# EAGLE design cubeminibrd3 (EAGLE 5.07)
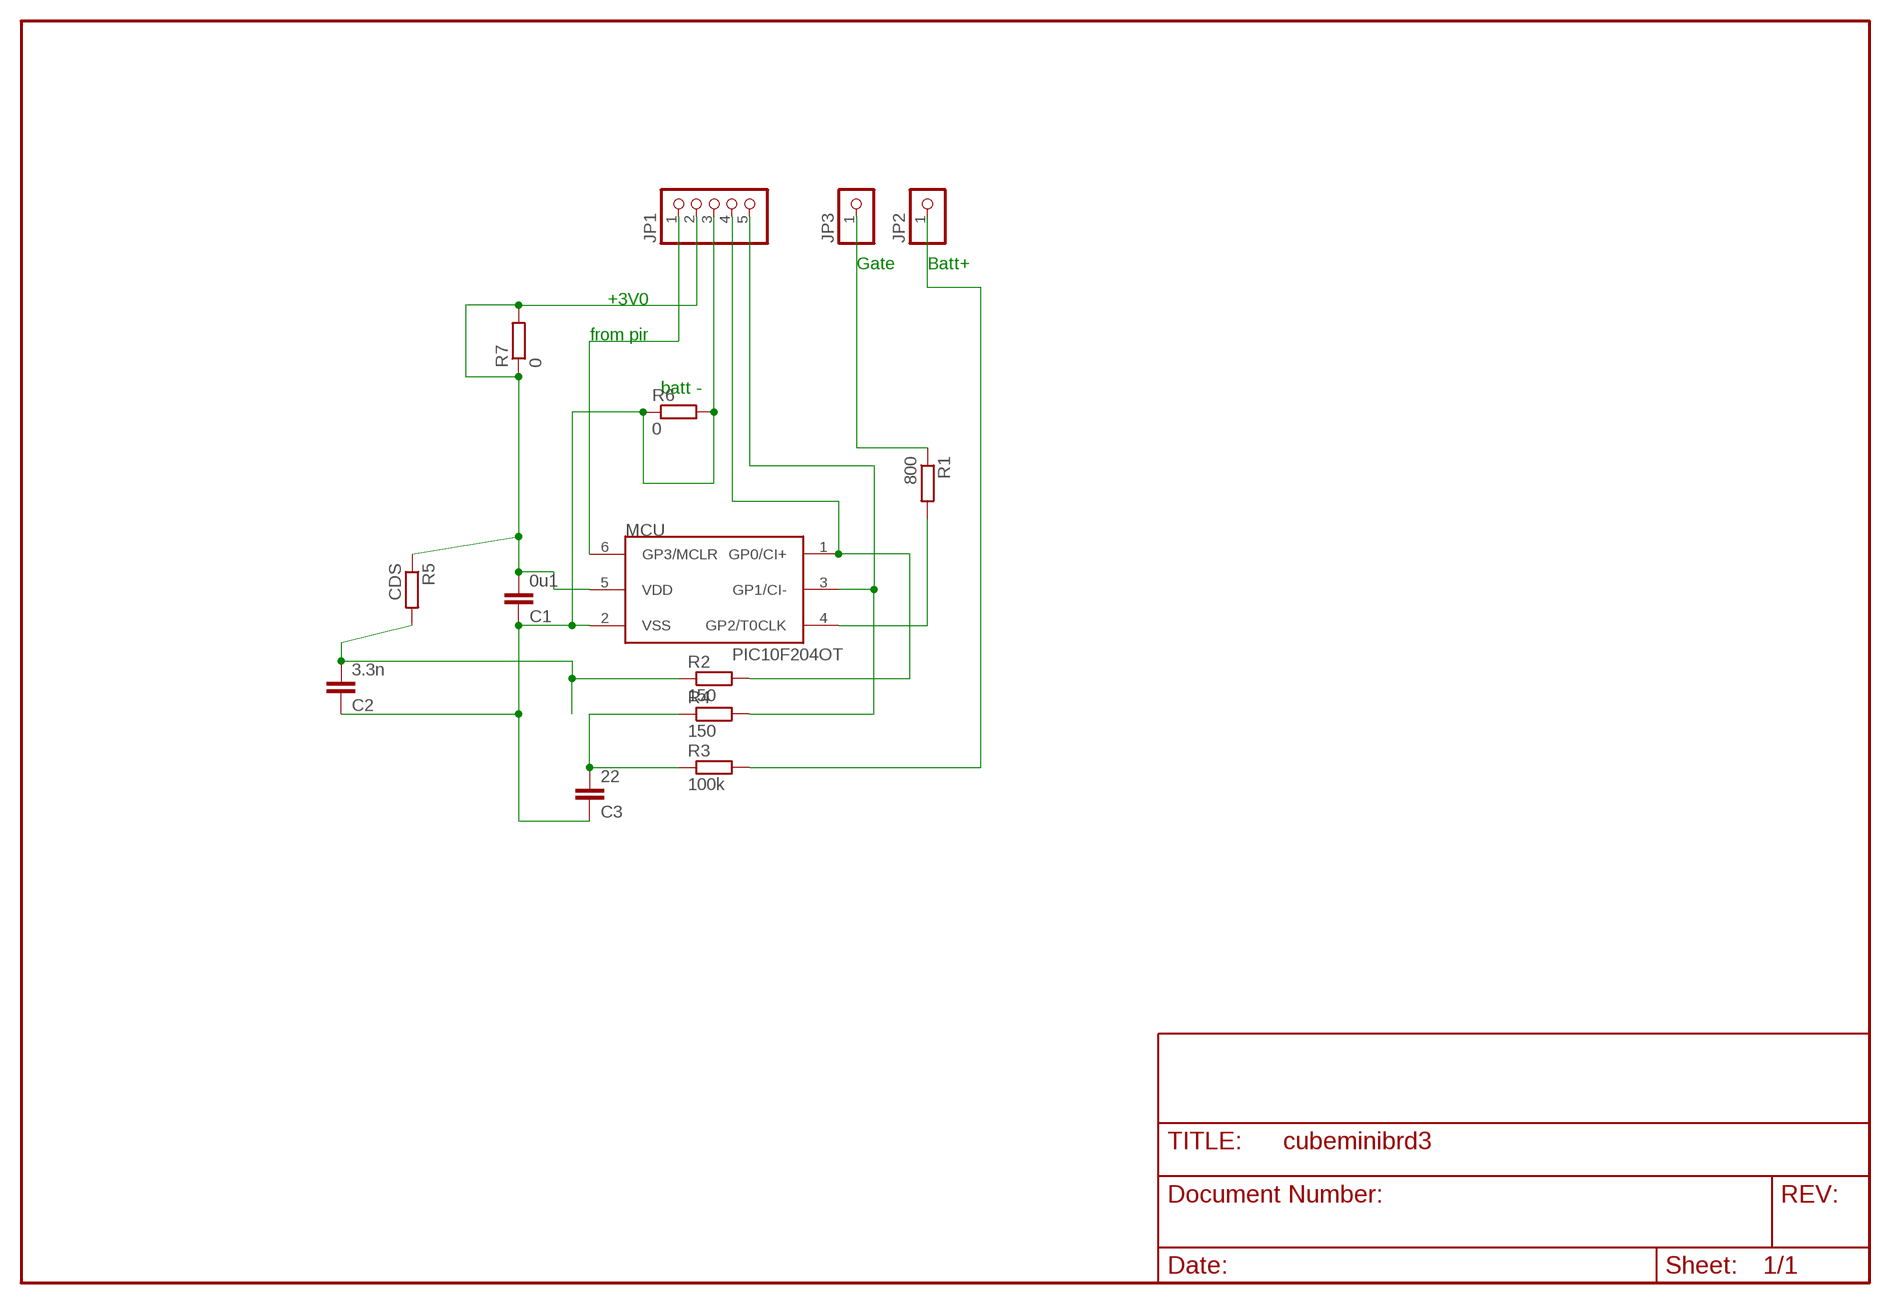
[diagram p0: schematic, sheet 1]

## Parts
C1  0u1  C-EUC1206  [C1206]
C2  3.3n  C-EUC1206  [C1206]
C3  22  C-EUC1206  [C1206]
JP1  PINHD-1X5  [1X05]
JP2  PINHD-1X1  [1X01]
JP3  PINHD-1X1  [1X01]
MCU  PIC10F204OT  [SOT23-6]
R1  800  R-EU_R1206  [R1206]
R2  150  R-EU_R1206  [R1206]
R3  100k  R-EU_R1206  [R1206]
R4  150  R-EU_R1206  [R1206]
R5  CDS  R-EU_0613/5V  [P0613V]
R6  0  R-EU_R1206  [R1206]
R7  0  R-EU_R1206  [R1206]

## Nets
N$1: JP3.1 R1.1
N$3: C2.2 R2.1 R5.2
N$4: JP1.4 MCU.1(GP0/CI+) R2.2
N$5: MCU.4(GP2/T0CLK) R1.2
N$7: C3.2 R3.1 R4.1
N$8: JP1.5 MCU.3(GP1/CI-) R4.2
PIR: JP1.1 MCU.6(GP3/MCLR)
V3: C1.2 JP1.2 MCU.5(VDD) R5.1 R7.1 R7.2
V+: JP2.1 R3.2
V-: C1.1 C2.1 C3.1 JP1.3 MCU.2(VSS) R6.1 R6.2

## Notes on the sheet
- Gate | Batt+
- +3V0
- from pir
- batt -

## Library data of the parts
C1-C3 = rcl:C-EU: CAPACITOR, European symbol
JP1 = pinhead:PINHD-1X5: PIN HEADER
JP2 JP3 = pinhead(2):PINHD-1X1: PIN HEADER
MCU = microchip-3:PIC10F2*: uPC nW 0,25/0,5k Program Flash memory Comparator
R1-R7 = rcl:R-EU_: RESISTOR, European symbol

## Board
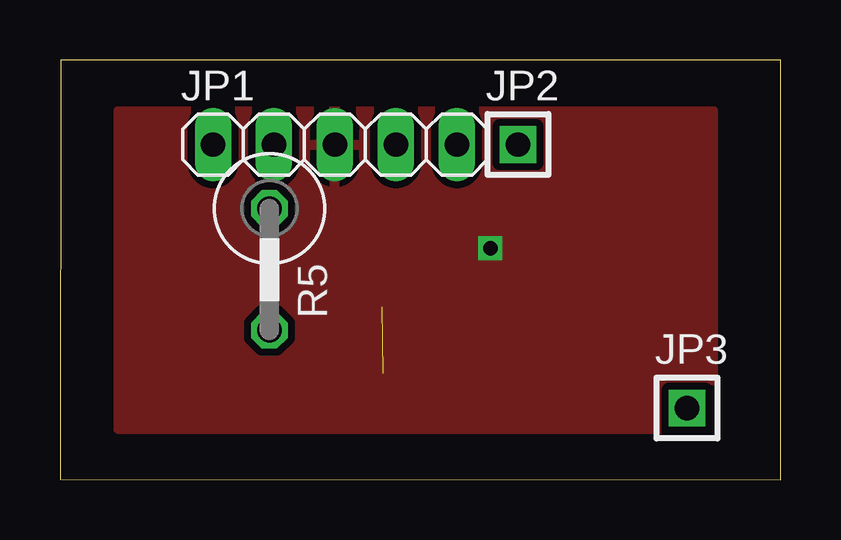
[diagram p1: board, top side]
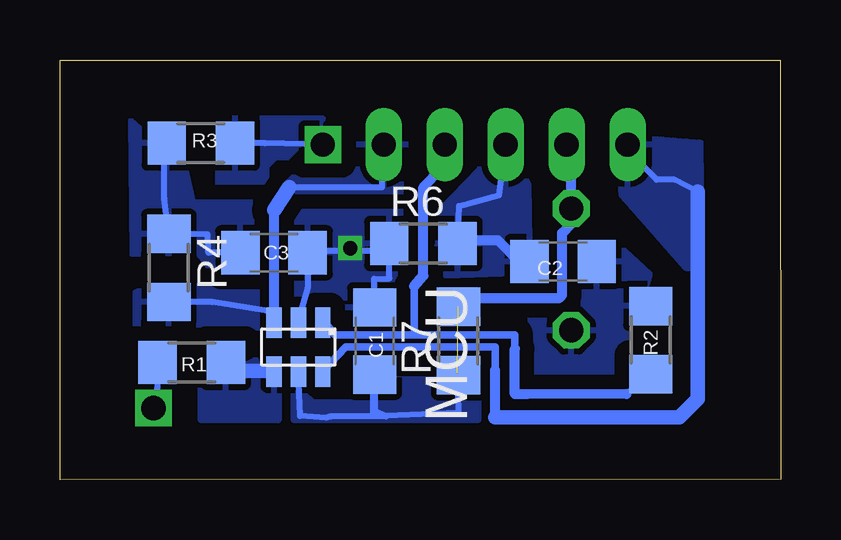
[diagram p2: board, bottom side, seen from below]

Size 30.03 x 17.5 mm. Coordinates in mm from the lower left corner, seen from the top.
Outline: 0,0.01 30.03,0 30.03,17.5 0.03,17.5 0,0.01
Copper layers (1*16): Top 0.035mm / dielectric 1.5mm / Bottom 0.035mm
Design rules "default": minimum track width 10mil, minimum drill 24mil, track to track 8mil, track to pad 8mil, pad to pad 8mil, via to via 8mil, smd to smd 8mil, copper to edge 1mil, drill to drill 8mil, minimum pad ring 10mil, minimum via ring 8mil, stop-mask expansion 4mil, vias tented up to drill 0mil, thermal gap 10mil

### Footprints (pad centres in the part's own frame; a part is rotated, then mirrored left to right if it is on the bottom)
C1206 = smd 1.6 x 1.8: 1 -1.4,0; 2 1.4,0
1X05 = drill 1.016 long: 1 -5.08,0; 2 -2.54,0; 3 0,0; 4 2.54,0; 5 5.08,0
1X01 = drill 1.016 square: 1 0,0
SOT23-6 = smd 0.635 x 1.27: 1 -1.016,-1.016; 2 0,-1.016; 3 1.016,-1.016; 4 1.016,1.016; 5 0,1.016; 6 -1.016,1.016
R1206 = smd 1.6 x 1.803: 1 -1.422,0; 2 1.422,0
P0613V = drill 1.016 octagon: 1 -2.54,0; 2 2.54,0

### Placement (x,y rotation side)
C1  16.92,5.78 270 bottom
C2  9.06,9.1 0 bottom
C3  21.11,9.46 180 bottom
JP1  11.46,13.97 0 top
JP2  19.08,13.97 0 top
JP3  26.12,2.98 0 top
MCU  20.09,5.52 180 bottom
R1  24.54,4.89 0 bottom
R2  5.41,5.82 270 bottom
R3  24.16,14.03 0 bottom
R4  25.49,8.83 270 bottom
R5  8.72,8.76 270 top
R6  14.88,9.84 0 bottom
R7  13.42,5.78 90 bottom

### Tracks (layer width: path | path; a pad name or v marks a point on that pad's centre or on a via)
N$1
  Bottom 0.254: R1.1 25.97,4.02 25.97,3.82 JP3.1
N$3
  pour Bottom (isolate 0.61): 7.01,10.03 10.63,6.67 10.63,4.13 7.39,4.13 6.76,4.64 5.42,8.57
N$4
  Bottom 0.254: 18.95,6.54 MCU.1 | R2.2 6.43,3.57 | 14.13,12.96 JP1.4
  Bottom 0.305: 18.95,6.54 18.57,6.03 15.27,6.03 | 15.27,6.03 11.07,6.03 11.07,5.46 | 15.27,6.03 15.27,8.06
  Bottom 0.406: 15.27,8.06 14.88,8.51 14.88,12.19 14.13,12.96 | 6.43,3.57 10.57,3.56 11.07,3.56 11.07,5.46
N$5
  Bottom 0.254: MCU.4 21.33,4.52 | 23.33,4.52 R1.2
  Bottom 0.61: 21.33,4.52 23.33,4.52
  pour Bottom: 20.92,3.81 20.92,2.48 24.16,2.48 24.16,3.87 21.87,5.02 21.68,3.81
N$7
  Bottom 0.254: R3.1 25.67,13.22 25.67,11.72 R4.1 23.87,10.22 23.85,9.46 C3.2
  pour Bottom (isolate 0.61, rank 2): 24.47,11.56 24.79,12.95 27.08,14.99 27.01,9.4 24.28,9.46 23.65,8.64 22,10.41 22,11.56
N$8
  Bottom 0.254: 16.6,14.35 | 16.6,14.35 JP1.5 | 20.47,12.19 16.6,12.19 16.6,14.35 | R4.2 23.68,7.4 21.37,7.02 MCU.3
  Bottom 0.406: MCU.3 21.11,11.24
  Bottom 0.61: 21.11,11.24 20.47,12.19
  pour Bottom (isolate 0.61): 21.81,8.06 26.38,8.06 26.89,7.81 26.89,6.35 26.76,6.16 21.81,6.16
  pour Bottom (isolate 0.61): 15.65,14.29 15.65,12 20.16,12 20.6,12.32 18.44,14.54
PIR
  Bottom 0.254: 3.45,12 4.41,12.51 5.17,12.51 6.28,13.62 JP1.1
  Bottom 0.305: MCU.6 18.12,5.52 11.9,5.52 11.9,4.57
  Bottom 0.406: 11.9,2.6 11.9,4.57
  Bottom 0.61: 11.9,2.6 4.22,2.6 3.45,3.37 3.45,12
  pour Bottom (isolate 0.61): 3.33,14.03 5.61,14.22 6.82,12.7 6.63,11.87 3.96,8.83 3.26,8.83
V3  (1 unrouted)
  Bottom 0.254: MCU.5 20.02,2.65 18.94,2.58 18.74,2.63 16.44,2.63 16.91,2.86 C1.2 16.98,3.75 16.98,2.64 13.43,2.77 13.47,4.42 R7.1
  Bottom 0.406: R7.2 13.13,7.56 9.23,7.56 9.11,7.68 9.11,10.29 8.73,10.67 R5.1 8.73,13.71 JP1.2
  pour Bottom: 12.6,4.19 12.6,2.48 20.28,2.48 20.28,3.62 19.9,3.62 19.52,3.24 17.74,3.24 17.36,4.19
V+
  Bottom 0.254: R3.2 21.97,14.02 21.47,14.02 JP2.1
  pour Bottom (isolate 0.61, rank 3): 19.08,15.05 23.46,15.05 23.46,12.32 21.68,12.32 19.2,14.8
V-  (via drill 0.6)
  Bottom 0.254: MCU.2 20.03,6.86 19.71,8 C3.1 18.93,9.52 16.17,9.52 R6.1 16.3,8.39 16.93,8.37 C1.1 | R6.2 13.39,11.41 11.73,11.86 JP1.3
  Bottom 0.406: C2.1 10.9,9.1 11.77,9.97 13.34,9.97 R6.2
  other vias: 17.93,9.65
  pour Bottom (isolate 0.61, rank 2): 15.58,11.3 15.58,6.67 18.12,6.67 18.89,7.75 20.35,7.75 20.35,11.3
  pour Bottom: 12.53,13.14 12.53,12.95 14.19,11.24 14.31,9.65 13.93,8.51 10.44,8.64 10.5,12.32 10.88,13.02 11.2,13.34
  pour Top (isolate 0.305): 2.44,15.37 27.2,15.37 27.2,2.1 2.44,2.1 2.44,14.73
